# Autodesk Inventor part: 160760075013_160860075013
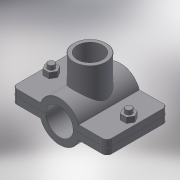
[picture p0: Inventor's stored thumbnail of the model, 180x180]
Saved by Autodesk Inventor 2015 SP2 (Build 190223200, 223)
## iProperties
Created: 2017-05
Part Number: 160760075013_160860075013
Material: Generic
Description: PLASSON SADDLE 75-1.1/4"
Document SubType Name: Modeling
Designer: KIM
Density: 1 g/cm^3
Appearance: Default
Author: KIM
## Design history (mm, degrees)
derived "16076.ipt"
feature "Solid1::16076.ipt"
feature "Solid2::16076.ipt"
tag "TaggingFeature1"
body "Solid1"
other parameters: "d0" = 93.75, "d1" = 122, "d2" = 37.5, "d3" = 75, "d4" = 98, "d5" = 0, "d6" = 6.1, "d7" = 122, "d8" = 0.1, "d10" = 0, "d11" = 0.75, "d14" = 50.6376, "d20" = 0.75, "d23" = 0.75, "d37" = 8, "d38" = 45.5, "d39" = 0, "d40" = 3, "d41" = 5, "d42" = 0, "d43" = 6, "d44" = 3, "d45" = 0, "d46" = 0.75, "d51" = 72, "d52" = 38.952, "d53" = 25, "d54" = 0, "d55" = 32, "d57" = 0, "d58" = 81, "d60" = 0, "d63" = 8, "d66" = 82, "d_" = 75, "B_" = 32, "G_" = 38.952, "A_" = 72, "L_" = 122, "L_1" = 98, "l_2" = 25
